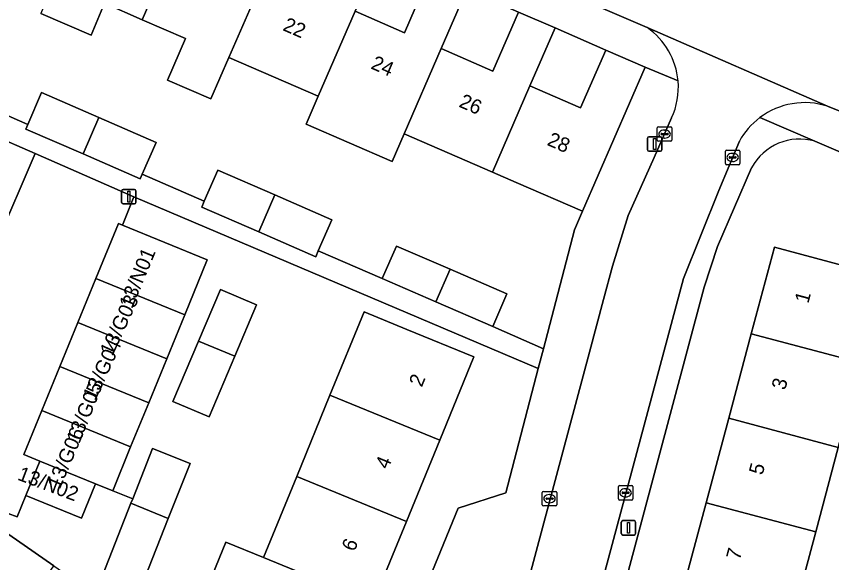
# Model space of a CAD drawing. Extents: x 162803 to 163818, y 381639 to 382475.
# Drawn here: x 163301.7 to 163358, y 381927.2 to 381965 of the extents above; entities that cross this region are included whole.
import ezdxf

# ---------------------------------------------------------------- set-up
doc = ezdxf.new("R2010")
doc.units = 0
for name, color, linetype in [('IMGEO_Erf', 7, 'Continuous'), ('IMGEO_Kolk', 7, 'Continuous'), ('IMGEO_Lichtmast', 7, 'Continuous'), ('IMGEO_Pand', 7, 'Continuous'), ('IMGEO_Pand_nummerreeks', 7, 'Continuous'), ('IMGEO_Rijbaan_lokaal_open', 7, 'Continuous'), ('IMGEO_Voetpad_open', 7, 'Continuous')]:
    doc.layers.add(name, color=color, linetype=linetype)

msp = doc.modelspace()

# ---------------------------------------------------------------- linework, layer by layer
at = {"layer": 'IMGEO_Erf'}
for points in [[(163326.897, 381969.448), (163325.099, 381965.314), (163328.51, 381963.831), (163330.299, 381967.946)], [(163336.405, 381965.257), (163332.835, 381966.844), (163331.045, 381962.73), (163334.629, 381961.172)], [(163338.923, 381964.162), (163337.185, 381960.16), (163340.685, 381958.639), (163342.419, 381962.629)], [(163337.762, 381940.645), (163309.811, 381952.487), (163309.024, 381950.542), (163314.886, 381948.141), (163313.334, 381944.351), (163312.088, 381941.309), (163310.843, 381938.267), (163309.598, 381935.225), (163308.358, 381932.197), (163309.738, 381931.65), (163311.106, 381935.117), (163313.706, 381934.091), (163312.199, 381930.271), (163310.033, 381924.777), (163325.4, 381914.344), (163332.221, 381930.991), (163335.518, 381932.057)], [(163356.934, 381929.351), (163355.377, 381923.515), (163353.825, 381917.699), (163357.548, 381916.765), (163355.972, 381910.858), (163352.263, 381911.843), (163350.706, 381906.007), (163349.11, 381900.027), (163341.536, 381902.048), (163343.132, 381908.028), (163344.689, 381913.865), (163346.247, 381919.701), (163347.804, 381925.536), (163349.361, 381931.371), (163350.919, 381937.209), (163352.476, 381943.044), (163354.072, 381949.025), (163361.645, 381947.004), (163365.541, 381945.965), (163363.945, 381939.984), (163360.049, 381941.022), (163358.491, 381935.186)], [(163316.799, 381941.491), (163315.018, 381937.295), (163312.521, 381938.354), (163314.288, 381942.519), (163315.806, 381946.095), (163318.302, 381945.036)], [(163323.368, 381938.801), (163325.723, 381944.553), (163328.684, 381943.341), (163333.311, 381941.446), (163330.956, 381935.694), (163328.658, 381930.083), (163326.361, 381924.472), (163324.007, 381918.723), (163319.38, 381920.618), (163316.419, 381921.83), (163313.815, 381922.896), (163316.169, 381928.645), (163318.773, 381927.579), (163321.07, 381933.19)], [(163306.42, 381922.605), (163302.91, 381925.033), (163304.283, 381927.018), (163296.762, 381932.249), (163296.673, 381932.282), (163291.676, 381934.146), (163284.175, 381936.467), (163283.558, 381934.136), (163279.55, 381935.197), (163275.54, 381936.258), (163276.157, 381938.589), (163265.939, 381941.198), (163262.719, 381928.933), (163262.737, 381927.272), (163262.993, 381926.715), (163263.886, 381925.565), (163279.163, 381915.031), (163284.116, 381911.615), (163313.54, 381891.287), (163316.437, 381892.468), (163324.747, 381912.749), (163311.302, 381922.163), (163309.929, 381920.178)]]:
    msp.add_lwpolyline(points, close=True, dxfattribs=at)
for points in [[(163300.541, 381958.336), (163302.488, 381957.49), (163303.447, 381959.695), (163307.4, 381957.977), (163311.353, 381956.259), (163310.395, 381954.055), (163314.683, 381952.192), (163315.617, 381954.341), (163319.554, 381952.63), (163323.491, 381950.918), (163322.558, 381948.77), (163326.983, 381946.848), (163327.959, 381949.099), (163331.672, 381947.49), (163335.591, 381945.791), (163334.615, 381943.54), (163338.117, 381942.001), (163340.262, 381950.209), (163340.821, 381951.498), (163336.236, 381953.491), (163334.594, 381954.205), (163328.491, 381956.858), (163327.66, 381954.948), (163321.719, 381957.526), (163322.55, 381959.44), (163316.388, 381962.119), (163315.144, 381959.258), (163312.152, 381960.558), (163313.396, 381963.42), (163310.39, 381964.726), (163307.779, 381965.861), (163306.866, 381963.652), (163303.388, 381965.164)], [(163394.019, 381926.474), (163393.907, 381926.523), (163389.411, 381928.473), (163387.886, 381929.134), (163388.608, 381930.798), (163382.581, 381933.411), (163376.439, 381936.074), (163370.425, 381938.682), (163373.829, 381946.533), (163370.045, 381948.172), (163370.933, 381950.319), (163356.875, 381956.335)], [(163352.498, 381954.506), (163350.15, 381949.06), (163349.232, 381946.25), (163337.135, 381901.001)]]:
    msp.add_lwpolyline(points, dxfattribs=at)
msp.add_arc((163355.818, 381952.712), 3.774, 73.743, 151.6138, dxfattribs=at)
at = {"layer": 'IMGEO_Kolk'}
for p, q in [((163345.986, 381956.405), (163345.986, 381957.257)), ((163346.061, 381957.331), (163346.913, 381957.331)), ((163346.474, 381957.111), (163346.499, 381957.111)), ((163346.987, 381957.257), (163346.987, 381956.405)), ((163346.245, 381956.825), (163346.245, 381956.837)), ((163346.683, 381956.788), (163346.285, 381956.788)), ((163346.288, 381956.874), (163346.686, 381956.874)), ((163346.497, 381956.551), (163346.472, 381956.551)), ((163346.729, 381956.837), (163346.729, 381956.825)), ((163346.913, 381956.331), (163346.061, 381956.331)), ((163350.688, 381954.792), (163350.688, 381955.644)), ((163350.763, 381955.718), (163351.615, 381955.718)), ((163350.99, 381955.261), (163351.388, 381955.261)), ((163351.176, 381955.498), (163351.201, 381955.498)), ((163351.689, 381955.644), (163351.689, 381954.792)), ((163351.615, 381954.718), (163350.763, 381954.718)), ((163350.947, 381955.212), (163350.947, 381955.224)), ((163351.385, 381955.175), (163350.987, 381955.175)), ((163351.199, 381954.938), (163351.174, 381954.938)), ((163351.431, 381955.224), (163351.431, 381955.212)), ((163338.112, 381932.153), (163338.964, 381932.153)), ((163343.293, 381931.63), (163343.293, 381932.482)), ((163343.368, 381932.556), (163344.22, 381932.556)), ((163343.781, 381932.336), (163343.806, 381932.336)), ((163344.294, 381932.482), (163344.294, 381931.63)), ((163338.037, 381931.227), (163338.037, 381932.079)), ((163338.296, 381931.647), (163338.296, 381931.659)), ((163338.734, 381931.61), (163338.336, 381931.61)), ((163338.339, 381931.696), (163338.737, 381931.696)), ((163338.525, 381931.933), (163338.55, 381931.933)), ((163338.78, 381931.659), (163338.78, 381931.647)), ((163339.038, 381932.079), (163339.038, 381931.227)), ((163343.552, 381932.05), (163343.552, 381932.062)), ((163343.99, 381932.013), (163343.592, 381932.013)), ((163343.595, 381932.099), (163343.993, 381932.099)), ((163343.804, 381931.776), (163343.779, 381931.776)), ((163344.036, 381932.062), (163344.036, 381932.05)), ((163338.964, 381931.153), (163338.112, 381931.153)), ((163338.548, 381931.373), (163338.523, 381931.373)), ((163344.22, 381931.556), (163343.368, 381931.556))]:
    msp.add_line(p, q, dxfattribs=at)
for points in [[(163345.986, 381956.405), (163345.986, 381957.257)], [(163346.061, 381957.331), (163346.913, 381957.331)], [(163346.987, 381957.257), (163346.987, 381956.405)], [(163346.913, 381956.331), (163346.061, 381956.331)], [(163350.688, 381954.792), (163350.688, 381955.644)], [(163350.763, 381955.718), (163351.615, 381955.718)], [(163351.689, 381955.644), (163351.689, 381954.792)], [(163351.615, 381954.718), (163350.763, 381954.718)], [(163338.112, 381932.153), (163338.964, 381932.153)], [(163343.293, 381931.63), (163343.293, 381932.482)], [(163343.368, 381932.556), (163344.22, 381932.556)], [(163344.294, 381932.482), (163344.294, 381931.63)], [(163338.037, 381931.227), (163338.037, 381932.079)], [(163339.038, 381932.079), (163339.038, 381931.227)], [(163338.964, 381931.153), (163338.112, 381931.153)], [(163344.22, 381931.556), (163343.368, 381931.556)]]:
    msp.add_lwpolyline(points, dxfattribs=at)
for centre, radius, start, end in [((163346.063, 381957.255), 0.0765, 91.552, 178.448), ((163346.063, 381957.255), 0.0765, 91.552, 178.448), ((163346.911, 381957.255), 0.0765, 1.552, 88.448), ((163346.911, 381957.255), 0.0765, 1.552, 88.448), ((163346.063, 381956.407), 0.0765, 181.552, 268.448), ((163346.063, 381956.407), 0.0765, 181.552, 268.448), ((163346.285, 381956.834), 0.0403, 85.8775, 175.7526), ((163346.282, 381956.824), 0.0366, 178.938, 274.7102), ((163346.686, 381956.831), 0.043, 264.8664, 352.4533), ((163346.69, 381956.836), 0.0386, 1.7309, 96.639), ((163346.911, 381956.407), 0.0765, 271.552, 358.448), ((163346.911, 381956.407), 0.0765, 271.552, 358.448), ((163350.765, 381955.642), 0.0765, 91.552, 178.448), ((163350.765, 381955.642), 0.0765, 91.552, 178.448), ((163350.987, 381955.221), 0.0403, 85.8775, 175.7526), ((163351.392, 381955.223), 0.0386, 1.7309, 96.639), ((163351.613, 381955.642), 0.0765, 1.552, 88.448), ((163351.613, 381955.642), 0.0765, 1.552, 88.448), ((163350.765, 381954.794), 0.0765, 181.552, 268.448), ((163350.765, 381954.794), 0.0765, 181.552, 268.448), ((163350.984, 381955.211), 0.0366, 178.938, 274.7102), ((163351.388, 381955.218), 0.043, 264.8664, 352.4533), ((163351.613, 381954.794), 0.0765, 271.552, 358.448), ((163351.613, 381954.794), 0.0765, 271.552, 358.448), ((163338.114, 381932.077), 0.0765, 91.552, 178.448), ((163338.114, 381932.077), 0.0765, 91.552, 178.448), ((163338.962, 381932.077), 0.0765, 1.552, 88.448), ((163338.962, 381932.077), 0.0765, 1.552, 88.448), ((163343.37, 381932.48), 0.0765, 91.552, 178.448), ((163343.37, 381932.48), 0.0765, 91.552, 178.448), ((163344.218, 381932.48), 0.0765, 1.552, 88.448), ((163344.218, 381932.48), 0.0765, 1.552, 88.448), ((163338.336, 381931.656), 0.0403, 85.8775, 175.7526), ((163338.333, 381931.646), 0.0366, 178.938, 274.7102), ((163338.737, 381931.653), 0.043, 264.8664, 352.4533), ((163338.741, 381931.658), 0.0386, 1.7309, 96.639), ((163343.37, 381931.632), 0.0765, 181.552, 268.448), ((163343.37, 381931.632), 0.0765, 181.552, 268.448), ((163343.592, 381932.059), 0.0403, 85.8775, 175.7526), ((163343.589, 381932.049), 0.0366, 178.938, 274.7102), ((163343.993, 381932.056), 0.043, 264.8664, 352.4533), ((163343.997, 381932.061), 0.0386, 1.7309, 96.639), ((163344.218, 381931.632), 0.0765, 271.552, 358.448), ((163344.218, 381931.632), 0.0765, 271.552, 358.448), ((163338.114, 381931.229), 0.0765, 181.552, 268.448), ((163338.114, 381931.229), 0.0765, 181.552, 268.448), ((163338.962, 381931.229), 0.0765, 271.552, 358.448), ((163338.962, 381931.229), 0.0765, 271.552, 358.448)]:
    msp.add_arc(centre, radius, start, end, dxfattribs=at)
for centre, major_axis, ratio, start_param, end_param in [((163346.473, 381956.831), (-0.387, 0.002), 0.722429, 4.712389, 7.853982), ((163346.498, 381956.831), (-0.39, 0.002), 0.717154, 1.570796, 4.712389), ((163351.175, 381955.218), (-0.387, 0.002), 0.722429, 4.712389, 7.853982), ((163351.2, 381955.218), (-0.39, 0.002), 0.717154, 1.570796, 4.712389), ((163343.78, 381932.056), (-0.387, 0.002), 0.722429, 4.712389, 7.853982), ((163343.805, 381932.056), (-0.39, 0.002), 0.717154, 1.570796, 4.712389), ((163338.524, 381931.653), (-0.387, 0.002), 0.722429, 4.712389, 7.853982), ((163338.549, 381931.653), (-0.39, 0.002), 0.717154, 1.570796, 4.712389)]:
    msp.add_ellipse(centre, major_axis=major_axis, ratio=ratio, start_param=start_param, end_param=end_param, dxfattribs=at)
at = {"layer": 'IMGEO_Lichtmast'}
for p, q in [((163345.31, 381955.745), (163345.31, 381956.545)), ((163345.31, 381956.545), (163345.31, 381955.745)), ((163345.41, 381956.645), (163346.2, 381956.645)), ((163346.2, 381956.645), (163345.41, 381956.645)), ((163346.3, 381956.545), (163346.3, 381955.745)), ((163346.3, 381955.745), (163346.3, 381956.545)), ((163346.2, 381955.645), (163345.41, 381955.645)), ((163345.41, 381955.645), (163346.2, 381955.645)), ((163309.075, 381953.007), (163309.865, 381953.007)), ((163309.865, 381953.007), (163309.075, 381953.007)), ((163308.975, 381952.107), (163308.975, 381952.907)), ((163308.975, 381952.907), (163308.975, 381952.107)), ((163309.965, 381952.907), (163309.965, 381952.107)), ((163309.965, 381952.107), (163309.965, 381952.907)), ((163309.865, 381952.007), (163309.075, 381952.007)), ((163309.075, 381952.007), (163309.865, 381952.007)), ((163343.498, 381929.236), (163343.498, 381930.036)), ((163343.498, 381930.036), (163343.498, 381929.236)), ((163343.598, 381930.136), (163344.388, 381930.136)), ((163344.388, 381930.136), (163343.598, 381930.136)), ((163344.488, 381930.036), (163344.488, 381929.236)), ((163344.488, 381929.236), (163344.488, 381930.036)), ((163344.388, 381929.136), (163343.598, 381929.136)), ((163343.598, 381929.136), (163344.388, 381929.136))]:
    msp.add_line(p, q, dxfattribs=at)
for points in [[(163345.73, 381956.52), (163345.88, 381956.52), (163345.88, 381955.77), (163345.73, 381955.77), (163345.73, 381956.52)], [(163309.395, 381952.882), (163309.545, 381952.882), (163309.545, 381952.132), (163309.395, 381952.132), (163309.395, 381952.882)], [(163343.918, 381930.011), (163344.068, 381930.011), (163344.068, 381929.261), (163343.918, 381929.261), (163343.918, 381930.011)]]:
    msp.add_lwpolyline(points, dxfattribs=at)
for centre, start, end in [((163345.41, 381956.545), 90, 180), ((163345.41, 381956.545), 90, 180), ((163346.2, 381956.545), 0, 90), ((163346.2, 381956.545), 360, 90), ((163345.41, 381955.745), 180, 270), ((163345.41, 381955.745), 180, 270), ((163346.2, 381955.745), 270, 0), ((163346.2, 381955.745), 270, 0), ((163309.075, 381952.907), 90, 180), ((163309.075, 381952.907), 90, 180), ((163309.865, 381952.907), 0, 90), ((163309.865, 381952.907), 360, 90), ((163309.075, 381952.107), 180, 270), ((163309.075, 381952.107), 180, 270), ((163309.865, 381952.107), 270, 0), ((163309.865, 381952.107), 270, 0), ((163343.598, 381930.036), 90, 180), ((163343.598, 381930.036), 90, 180), ((163344.388, 381930.036), 0, 90), ((163344.388, 381930.036), 360, 90), ((163343.598, 381929.236), 180, 270), ((163343.598, 381929.236), 180, 270), ((163344.388, 381929.236), 270, 0), ((163344.388, 381929.236), 270, 0)]:
    msp.add_arc(centre, 0.1, start, end, dxfattribs=at)
at = {"layer": 'IMGEO_Pand'}
for points in [[(163310.39, 381964.726), (163312.956, 381970.637), (163314.721, 381974.698), (163312.073, 381975.849), (163310.306, 381971.785), (163306.847, 381973.288), (163304.301, 381967.373), (163303.388, 381965.164), (163306.866, 381963.652), (163307.779, 381965.861)], [(163320.72, 381972.101), (163318.209, 381973.193), (163316.439, 381969.122), (163312.956, 381970.637), (163310.39, 381964.726), (163313.396, 381963.42), (163312.152, 381960.558), (163315.144, 381959.258), (163316.388, 381962.119), (163318.96, 381968.044)], [(163322.55, 381959.44), (163325.099, 381965.314), (163326.897, 381969.448), (163324.189, 381970.625), (163322.415, 381966.543), (163318.96, 381968.044), (163316.388, 381962.119)], [(163331.045, 381962.73), (163332.835, 381966.844), (163330.299, 381967.946), (163328.51, 381963.831), (163325.099, 381965.314), (163322.55, 381959.44), (163321.719, 381957.526), (163327.66, 381954.948), (163328.491, 381956.858)], [(163338.923, 381964.162), (163336.405, 381965.257), (163334.629, 381961.172), (163331.045, 381962.73), (163328.491, 381956.858), (163334.594, 381954.205), (163337.185, 381960.16)], [(163334.594, 381954.205), (163336.236, 381953.491), (163340.821, 381951.498), (163345.145, 381961.444), (163342.419, 381962.629), (163340.685, 381958.639), (163337.185, 381960.16)], [(163307.4, 381957.977), (163303.447, 381959.695), (163302.488, 381957.49), (163302.352, 381957.176), (163306.305, 381955.457)], [(163307.4, 381957.977), (163306.305, 381955.457), (163310.258, 381953.739), (163310.395, 381954.055), (163311.353, 381956.259)], [(163297.235, 381950.668), (163300.324, 381949.325), (163302.999, 381955.478), (163299.91, 381956.821)], [(163319.554, 381952.63), (163315.617, 381954.341), (163314.683, 381952.192), (163314.506, 381951.786), (163318.443, 381950.075)], [(163319.554, 381952.63), (163318.443, 381950.075), (163322.381, 381948.363), (163322.558, 381948.77), (163323.491, 381950.918)], [(163307.195, 381946.864), (163313.334, 381944.351), (163314.886, 381948.141), (163309.024, 381950.542), (163308.747, 381950.655)], [(163331.672, 381947.49), (163327.959, 381949.099), (163326.983, 381946.848), (163330.693, 381945.24)], [(163352.476, 381943.044), (163360.049, 381941.022), (163363.945, 381939.984), (163365.541, 381945.965), (163361.645, 381947.004), (163354.072, 381949.025)], [(163331.672, 381947.49), (163330.693, 381945.24), (163334.615, 381943.54), (163335.591, 381945.791)], [(163312.088, 381941.309), (163313.334, 381944.351), (163307.195, 381946.864), (163305.95, 381943.822)], [(163314.288, 381942.519), (163316.799, 381941.491), (163318.302, 381945.036), (163315.806, 381946.095)], [(163323.368, 381938.801), (163330.956, 381935.694), (163333.311, 381941.446), (163328.684, 381943.341), (163325.723, 381944.553)], [(163310.843, 381938.267), (163312.088, 381941.309), (163305.95, 381943.822), (163304.704, 381940.78)], [(163350.919, 381937.209), (163358.491, 381935.186), (163360.049, 381941.022), (163352.476, 381943.044)], [(163314.288, 381942.519), (163312.521, 381938.354), (163315.018, 381937.295), (163316.799, 381941.491)], [(163304.704, 381940.78), (163303.458, 381937.739), (163309.598, 381935.225), (163310.843, 381938.267)], [(163323.368, 381938.801), (163321.07, 381933.19), (163328.658, 381930.083), (163330.956, 381935.694)], [(163303.458, 381937.739), (163302.213, 381934.697), (163303.327, 381934.241), (163307.172, 381932.682), (163308.358, 381932.197), (163309.598, 381935.225)], [(163350.919, 381937.209), (163349.361, 381931.371), (163356.934, 381929.351), (163358.491, 381935.186)], [(163313.706, 381934.091), (163311.106, 381935.117), (163309.738, 381931.65), (163309.612, 381931.33), (163312.199, 381930.271)], [(163307.172, 381932.682), (163303.327, 381934.241), (163302.355, 381931.866), (163306.194, 381930.294)], [(163321.07, 381933.19), (163318.773, 381927.579), (163326.361, 381924.472), (163328.658, 381930.083)], [(163312.199, 381930.271), (163309.612, 381931.33), (163307.643, 381926.338), (163310.033, 381924.777)], [(163347.804, 381925.536), (163355.377, 381923.515), (163356.934, 381929.351), (163349.361, 381931.371)], [(163326.361, 381924.472), (163318.773, 381927.579), (163316.169, 381928.645), (163313.815, 381922.896), (163316.419, 381921.83), (163319.38, 381920.618), (163324.007, 381918.723)]]:
    msp.add_lwpolyline(points, close=True, dxfattribs=at)
at = {"layer": 'IMGEO_Rijbaan_lokaal_open'}
msp.add_lwpolyline([(163360.196, 381965.225), (163337.225, 381975.21), (163334.486, 381968.838), (163345.294, 381964.18), (163357.753, 381958.749), (163359.789, 381957.922), (163393.809, 381943.083), (163396.507, 381949.508), (163370.112, 381960.939)], close=True, dxfattribs=at)
for points in [[(163357.753, 381958.749), (163345.294, 381964.18)], [(163346.974, 381957.941), (163345.777, 381955.212), (163343.979, 381951.2), (163342.879, 381947.698), (163342.269, 381945.397), (163341.305, 381941.763), (163328.227, 381892.894), (163326.344, 381885.984), (163331.151, 381884.601), (163332.971, 381891.319), (163334.132, 381895.953), (163335.318, 381900.38), (163335.427, 381900.82), (163336.429, 381904.454), (163347.786, 381946.853)], [(163347.786, 381946.853), (163350.24, 381952.934), (163351.653, 381956.334)], [(163296.762, 381932.249), (163301.752, 381930.388), (163302.355, 381931.866), (163303.327, 381934.241), (163302.213, 381934.697), (163303.458, 381937.739), (163304.704, 381940.78), (163305.95, 381943.822), (163307.195, 381946.864), (163308.747, 381950.655), (163309.024, 381950.542), (163309.811, 381952.487), (163302.999, 381955.478), (163300.324, 381949.325)]]:
    msp.add_lwpolyline(points, dxfattribs=at)
for centre, radius, start, end in [((163342.403, 381960.055), 5.037, 5.0999, 54.9722), ((163342.396, 381960.058), 5.044, 335.1853, 5.0642), ((163356.163, 381953.855), 5.146, 72.0048, 126.9912), ((163356.137, 381953.875), 5.114, 126.8922, 151.2603)]:
    msp.add_arc(centre, radius, start, end, dxfattribs=at)
at = {"layer": 'IMGEO_Voetpad_open'}
for points in [[(163278.579, 381990.44), (163281.713, 381989.031), (163297.883, 381982.108), (163301.045, 381980.736), (163302.664, 381980.008), (163306.036, 381978.49), (163308.618, 381977.367), (163312.073, 381975.849), (163314.721, 381974.698), (163318.209, 381973.193), (163320.72, 381972.101), (163324.189, 381970.625), (163326.897, 381969.448), (163330.299, 381967.946), (163332.835, 381966.844), (163336.405, 381965.257), (163338.923, 381964.162), (163342.419, 381962.629), (163345.145, 381961.444), (163347.42, 381960.503)], [(163345.294, 381964.18), (163334.486, 381968.838), (163331.307, 381970.219), (163302.214, 381982.84)], [(163347.42, 381960.503), (163345.145, 381961.444), (163340.821, 381951.498), (163340.262, 381950.209), (163338.117, 381942.001), (163337.762, 381940.645), (163335.518, 381932.057), (163332.221, 381930.991), (163325.4, 381914.344), (163324.747, 381912.749), (163316.437, 381892.468), (163312.179, 381886.77), (163312.585, 381885.073)], [(163359.789, 381957.922), (163357.753, 381958.749)], [(163299.91, 381956.821), (163302.999, 381955.478), (163309.811, 381952.487), (163337.762, 381940.645), (163338.117, 381942.001), (163334.615, 381943.54), (163330.693, 381945.24), (163326.983, 381946.848), (163322.558, 381948.77), (163322.381, 381948.363), (163318.443, 381950.075), (163314.506, 381951.786), (163314.683, 381952.192), (163310.395, 381954.055), (163310.258, 381953.739), (163306.305, 381955.457), (163302.352, 381957.176), (163302.488, 381957.49), (163300.541, 381958.336)], [(163341.305, 381941.763), (163342.269, 381945.397), (163342.879, 381947.698), (163343.979, 381951.2), (163345.777, 381955.212), (163346.974, 381957.941)], [(163356.875, 381956.335), (163353.067, 381957.965)], [(163353.067, 381957.965), (163356.875, 381956.335), (163370.933, 381950.319), (163374.748, 381948.652), (163377.31, 381947.532), (163380.761, 381946.058), (163383.357, 381944.932), (163386.888, 381943.344), (163389.416, 381942.248), (163392.933, 381940.714), (163395.546, 381939.582), (163398.934, 381938.133), (163401.592, 381936.98), (163408.469, 381934.011)], [(163351.653, 381956.334), (163350.24, 381952.934), (163347.786, 381946.853), (163336.429, 381904.454), (163336.85, 381904.347), (163335.864, 381900.697), (163335.427, 381900.82), (163335.318, 381900.38), (163336.323, 381900.111), (163335.137, 381895.684), (163334.132, 381895.953), (163332.971, 381891.319), (163331.151, 381884.601), (163329.883, 381879.737), (163332.261, 381878.421), (163331.869, 381881.301), (163336.733, 381899.497), (163337.135, 381901.001), (163349.232, 381946.25)], [(163349.232, 381946.25), (163350.15, 381949.06), (163352.498, 381954.506)], [(163326.012, 381884.905), (163326.344, 381885.984), (163328.227, 381892.894), (163341.305, 381941.763)]]:
    msp.add_lwpolyline(points, dxfattribs=at)
msp.add_lwpolyline([(163309.612, 381931.33), (163309.738, 381931.65), (163308.358, 381932.197), (163307.172, 381932.682), (163306.194, 381930.294), (163302.355, 381931.866), (163301.752, 381930.388), (163296.762, 381932.249), (163304.283, 381927.018), (163307.793, 381924.59), (163311.302, 381922.163), (163324.747, 381912.749), (163325.4, 381914.344), (163310.033, 381924.777), (163307.643, 381926.338)], close=True, dxfattribs=at)
for centre, radius, start, end in [((163342.403, 381960.055), 5.037, 5.0999, 54.9722), ((163342.396, 381960.058), 5.044, 335.1853, 5.0642), ((163356.163, 381953.855), 5.146, 72.0048, 126.9912), ((163356.137, 381953.875), 5.114, 126.8922, 151.2603), ((163355.818, 381952.712), 3.774, 73.743, 151.6138)]:
    msp.add_arc(centre, radius, start, end, dxfattribs=at)

# ---------------------------------------------------------------- texts
at = {"layer": 'IMGEO_Pand_nummerreeks'}
for s, rotation, p in [('22', 336.5335, (163320.049, 381964.02)), ('24', 336.5316, (163326.135, 381961.377)), ('26', 336.5316, (163332.219, 381958.736)), ('28', 336.5335, (163338.308, 381956.094)), ('13/N01', 67.3801, (163309.686, 381944.721)), ('13/G03', 65.1576, (163308.333, 381941.449)), ('1', 75.0586, (163356.416, 381945.087)), ('13/G04', 65.0952, (163307.145, 381938.372)), ('2', 67.7332, (163329.711, 381939.304)), ('13/G05', 68.1986, (163306.047, 381935.399)), ('3', 75.0586, (163354.819, 381939.105)), ('13/G06', 66.9149, (163304.699, 381932.256)), ('4', 67.7332, (163327.386, 381933.625)), ('5', 75.0586, (163353.252, 381933.233)), ('13/N02', 339.3159, (163301.718, 381932.974)), ('6', 67.7332, (163325.06, 381927.944)), ('7', 75.0586, (163351.685, 381927.361))]:
    msp.add_text(s, height=1, rotation=rotation, dxfattribs=at).set_placement(p)

doc.saveas('drawing.dxf')
